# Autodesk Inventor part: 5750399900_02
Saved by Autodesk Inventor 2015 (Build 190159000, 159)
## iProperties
Created: 2020-07
Part Number: 5750399900_02
Checked By: TraceParts S.A.
Material: Generic
Catalog Web Link: www.traceparts.com
Document SubType Name: Modeling
Designer: TraceParts
Density: 1 g/cm^3
Appearance: Default
Company: TraceParts S.A.
Author: TraceParts
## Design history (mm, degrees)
feature "5750399900_02.ipt"
body "Solid1"
